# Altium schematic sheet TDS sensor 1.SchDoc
size A4; DocumentNumber: 4; SheetNumber: 4; SheetTotal: 4
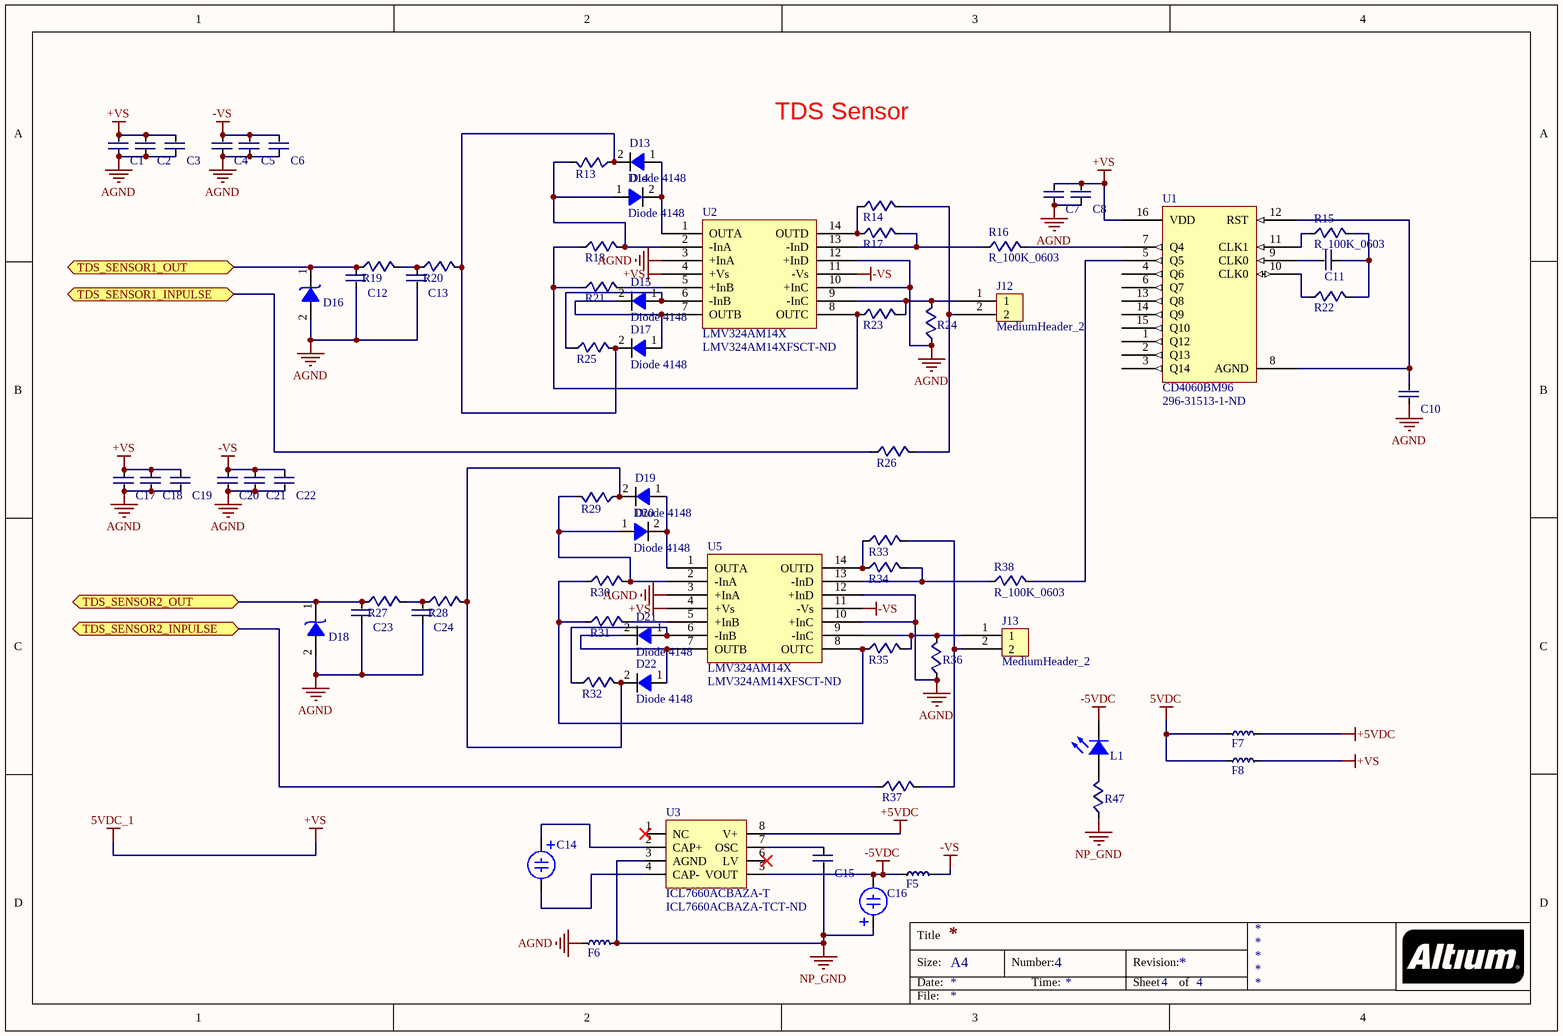
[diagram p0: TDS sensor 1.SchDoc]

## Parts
C1  100n Cer  [CN-SMD-0805]  (value not drawn)
C2  1n Cer  [CN-SMD-0805]  (value not drawn)
C3  10n Cer  [CN-SMD-0805]  (value not drawn)
C4  100n Cer  [CN-SMD-0805]  (value not drawn)
C5  1n Cer  [CN-SMD-0805]  (value not drawn)
C6  10n Cer  [CN-SMD-0805]  (value not drawn)
C7  10n Cer  [CN-SMD-0805]  (value not drawn)
C8  100n Cer  [CN-SMD-0805]  (value not drawn)
C10  100n Cer  [CN-SMD-0805]  (value not drawn)
C11  1n Cer  [CN-SMD-0805]  (value not drawn)
C12  10u Cer  [CN-SMD-0805]  (value not drawn)
C13  10u Cer  [CN-SMD-0805]  (value not drawn)
C14  CAP ALUM 100UF 25V 20% SMDL  [CAPALU_SM_5.3x5.3]  (value not drawn)
C15  100n Cer  [CN-SMD-0805]  (value not drawn)
C16  CAP ALUM 100UF 25V 20% SMDL  [CAPALU_SM_5.3x5.3]  (value not drawn)
C17  100n Cer  [CN-SMD-0805]  (value not drawn)
C18  1n Cer  [CN-SMD-0805]  (value not drawn)
C19  10n Cer  [CN-SMD-0805]  (value not drawn)
C20  100n Cer  [CN-SMD-0805]  (value not drawn)
C21  1n Cer  [CN-SMD-0805]  (value not drawn)
C22  10n Cer  [CN-SMD-0805]  (value not drawn)
C23  10u Cer  [CN-SMD-0805]  (value not drawn)
C24  10u Cer  [CN-SMD-0805]  (value not drawn)
D13  Diode 4148  [CD3216-1206]
D14  Diode 4148  [CD3216-1206]
D15  Diode 4148  [CD3216-1206]
D16  Diode_SS34  [DO-214AB_MOD_EXT]  (value not drawn)
D17  Diode 4148  [CD3216-1206]
D18  Diode_SS34  [DO-214AB_MOD_EXT]  (value not drawn)
D19  Diode 4148  [CD3216-1206]
D20  Diode 4148  [CD3216-1206]
D21  Diode 4148  [CD3216-1206]
D22  Diode 4148  [CD3216-1206]
F5  FBFB0805  [RESC_0603]  (value not drawn)
F6  FBFB0805  [RESC_0603]  (value not drawn)
F7  FBFB0805  [RESC_0603]  (value not drawn)
F8  FBFB0805  [RESC_0603]  (value not drawn)
J12  MediumHeader_2  [Medium - Header 2]
J13  MediumHeader_2  [Medium - Header 2]
L1  LTST-C171KRKT  [LED_0805]  (value not drawn)
R13  R_10K_0603  [RES-SMD-0603]  (value not drawn)
R14  R_0R_0603  [RES-SMD-0603]  (value not drawn)
R15  R_100K_0603  [RES-SMD-0603]
R16  R_100K_0603  [RES-SMD-0603]
R17  R_4K99_0603  [RES-SMD-0603]  (value not drawn)
R18  R_10K_0603  [RES-SMD-0603]  (value not drawn)
R19  R_10K_0603  [RES-SMD-0603]  (value not drawn)
R20  R_10K_0603  [RES-SMD-0603]  (value not drawn)
R21  R_10K_0603  [RES-SMD-0603]  (value not drawn)
R22  R_10K_0603  [RES-SMD-0603]  (value not drawn)
R23  R_4K99_0603  [RES-SMD-0603]  (value not drawn)
R24  R_1M_0603  [RES-SMD-0603]  (value not drawn)
R25  R_10K_0603  [RES-SMD-0603]  (value not drawn)
R26  R_0R_0603  [RES-SMD-0603]  (value not drawn)
R27  R_10K_0603  [RES-SMD-0603]  (value not drawn)
R28  R_10K_0603  [RES-SMD-0603]  (value not drawn)
R29  R_10K_0603  [RES-SMD-0603]  (value not drawn)
R30  R_10K_0603  [RES-SMD-0603]  (value not drawn)
R31  R_10K_0603  [RES-SMD-0603]  (value not drawn)
R32  R_10K_0603  [RES-SMD-0603]  (value not drawn)
R33  R_0R_0603  [RES-SMD-0603]  (value not drawn)
R34  R_4K99_0603  [RES-SMD-0603]  (value not drawn)
R35  R_4K99_0603  [RES-SMD-0603]  (value not drawn)
R36  R_1M_0603  [RES-SMD-0603]  (value not drawn)
R37  R_0R_0603  [RES-SMD-0603]  (value not drawn)
R38  R_100K_0603  [RES-SMD-0603]
R47  R_560R_0603  [RES-SMD-0603]  (value not drawn)
U1  CD4060BM96  Supplier Part Number 1: 296-31513-1-ND  [SOIC_16]
U2  LMV324AM14X  Supplier Part Number 1: LMV324AM14XFSCT-ND  [SOIC-14]
U3  ICL7660ACBAZA-T  Supplier Part Number 1: ICL7660ACBAZA-TCT-ND  [SOIC-8_MOD_24LC128]
U5  LMV324AM14X  Supplier Part Number 1: LMV324AM14XFSCT-ND  [SOIC-14]

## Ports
TDS_SENSOR1_INPULSE, TDS_SENSOR1_OUT, TDS_SENSOR2_INPULSE, TDS_SENSOR2_OUT

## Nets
5VDC: F7.1 F8.1
+5VDC: F7.2 U3.8(V+)
+VS: C1.2 C2.2 C3.2 C7.2 C8.2 C17.2 C18.2 C19.2 F8.2 U1.16(VDD) U2.4(+Vs) U5.4(+Vs)  [also labelled 5VDC_1]
-5VDC: C16.2 F5.1 L1.2(K) U3.5(VOUT)
-VS: C4.2 C5.2 C6.2 C20.2 C21.2 C22.2 F5.2 U2.11(-Vs) U5.11(-Vs)
AGND: C1.1 C2.1 C3.1 C4.1 C5.1 C6.1 C7.1 C8.1 C10.1 C12.1 C13.1 C17.1 C18.1 C19.1 C20.1 C21.1 C22.1 C23.1 C24.1 D16.2 D18.2 F6.1 R24.1 R36.1 U2.3(+InA) U2.10(+InC) U2.12(+InD) U5.3(+InA) U5.10(+InC) U5.12(+InD)
NP_GND: C15.1 C16.1 F6.2 R47.1 U3.3(AGND)
TDS_SENSOR1_INPULSE: R26.1 ; port TDS_SENSOR1_INPULSE
TDS_SENSOR1_OUT: C12.2 D16.1 R19.1 ; port TDS_SENSOR1_OUT
TDS_SENSOR2_INPULSE: R37.1 ; port TDS_SENSOR2_INPULSE
TDS_SENSOR2_OUT: C23.2 D18.1 R27.1 ; port TDS_SENSOR2_OUT
NetC10_2: C10.2 U1.8(AGND) U1.12(RST)
NetC11_1: C11.1 U1.9(CLK0)
NetC11_2: C11.2 R15.2 R22.2
NetC13_2: C13.2 R19.2 R20.1
NetC14_1: C14.1 U3.2(CAP+)
NetC14_2: C14.2 U3.4(CAP-)
NetC15_2: C15.2 U3.7(OSC)
NetC24_2: C24.2 R27.2 R28.1
NetD13_1: D13.1 D14.2 U2.1(OUTA)
NetD13_2: D13.2 D17.2 R13.1 R20.2 R25.2
NetD14_1: D14.1 R13.2 R18.2 U2.2(-InA)
NetD15_1: D15.1 R25.1 U2.6(-InB)
NetD15_2: D15.2 D17.1 U2.7(OUTB)
NetD19_1: D19.1 D20.2 U5.1(OUTA)
NetD19_2: D19.2 D22.2 R28.2 R29.1 R32.2
NetD20_1: D20.1 R29.2 R30.2 U5.2(-InA)
NetD21_1: D21.1 R32.1 U5.6(-InB)
NetD21_2: D21.2 D22.1 U5.7(OUTB)
NetJ12_1: J12.1 R23.2 R24.2 U2.9(-InC)
NetJ12_2: J12.2 R14.2 R26.2
NetJ13_1: J13.1 R35.2 R36.2 U5.9(-InC)
NetJ13_2: J13.2 R33.2 R37.2
NetL1_1: L1.1(A) R47.2
NetR14_1: R14.1 R17.1 U2.14(OUTD)
NetR15_1: R15.1 U1.11(CLK1)
NetR16_1: R16.1 R17.2 U2.13(-InD)
NetR16_2: R16.2 U1.7(Q4)
NetR18_1: R18.1 R21.1 R23.1 U2.8(OUTC)
NetR21_2: R21.2 U2.5(+InB)
NetR22_1: R22.1 U1.10(CLK0)
NetR30_1: R30.1 R31.1 R35.1 U5.8(OUTC)
NetR31_2: R31.2 U5.5(+InB)
NetR33_1: R33.1 R34.1 U5.14(OUTD)
NetR34_2: R34.2 R38.1 U5.13(-InD)
NetR38_2: R38.2 U1.5(Q5)

Not connected (* = marked no-connect by the designer): U1 1(Q12) 2(Q13) 3(Q14) 4(Q6) 6(Q7) 13(Q8) 14(Q9) 15(Q10); U3 1(NC)* 6(LV)*

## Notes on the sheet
- TDS Sensor

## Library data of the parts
C1 C4 C8 C10 C15 C17 C20 = CAPC0805_104: CAP CER 0.1UF 25V 10% X7R 0805
C2 C5 C11 C18 C21 = CAPC0805_102: CAP CER 1000PF 50V 10% X7R 0805
C3 C6 C7 C19 C22 = CAPC0805_103: CAP CER 10000PF 100V X7R 0805
C12 C13 C23 C24 = CAPC0805_106: CAP CER 10UF 6.3V 10% X7R 0805
C14 C16 = CAPALU100U25V: CAP ALUM 100UF 25V 20% SMD
D13-D15 D17 D19-D22 = Diode_4148: DIODE SWITCHING 75V 0.2A LLDS
D16 D18 = Diode_SS34: DIODE SCHOTTKY 40V 3A SMC
F5-F8 = FB0603_1000Ohm: FERRITE BEAD 1000 OHM 0603
L1 = LED0805_RED: LED RED CLEAR 0805 SMD; Manufacturer: Generic Components; Class: Optoelectronic
R13 R18-R22 R25 R27-R32 = RES0603_10K: RES 10.0K OHM 1/10W 1% 0603 SMD
R14 R26 R33 R37 = RES0603_0R: RES 0.0 OHM 1/10W JUMP 0603 SMD
R15 R16 R38 = RES0603_100K: RES 100K OHM 1/10W 1% 0603 SMD
R17 R23 R34 R35 = RES0603_4K99: RES 4.99K OHM 1/10W 1% 0603 SMD
R24 R36 = RES0603_1M: RES 1M OHM 1/8W 1% 0603 SMD
R47 = RES0603_560R: RES 560 OHM 1/10W 0603 SMD
U1 = CD4060BM: IC BINARY COUNTER/DIV/OSC 16SOIC
U2 U5 = LMV324A: IC OPAMP VFB 1.4MHZ RRO 14SOIC
U3 = ICL7660: IC REG SWTCHD CAP INV 45MA 8SOIC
